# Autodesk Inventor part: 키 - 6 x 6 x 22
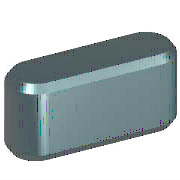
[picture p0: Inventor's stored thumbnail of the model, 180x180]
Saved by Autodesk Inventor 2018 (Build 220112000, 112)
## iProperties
IsCustomPart: 1
Created: 2012-02
Part Number: 키 - 6 x 6 x 22
Material: 강철, 연강
Description: 키 및 해당 키홈
Document SubType Name: Modeling
Standard: KS B 1311
Designer: mduedu
Standards Organization: KS
Language: ko-KR
Size Designation: 6 x 6 x 22
Categories: <MemberInstance><Categories><Category DisplayName="샤프트 부품" InternalName="7f7aeb1f-a693-4053-b835-cee3144e0d98" Mnemonic="SHFT"><Category DisplayName="키" Interna
Density: 7.86 g/cm^3
Mass: 5.79788 g
Surface Area: 5.294 cm^2
Volume: 0.737644 cm^3
Appearance: 노란색
Author: mduedu
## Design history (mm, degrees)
workplane "Work Plane1"
workplane "Work Plane2"
sketch "스케치1"
  geometry: L1 (3, 3)-(19, 3); L2 (19, -3)-(3, -3); L3 (0, 9.4)-(0, -7.4) reference; L4 (-5, 0)-(30, 0) reference; L5 (22, 0)-(22, 7); A1 r 3 centre (3, 0) between (3, 3) and (3, -3); A2 r 3 centre (19, 0) between (19, -3) and (19, 3)
  constraints: 6 end point, 5 point on circle, 4 tangent, 3 point on line, 2 centre point, 1 horizontal, 1 parallel, 1 perpendicular
  dimensions: "d0" = 3 radius of A1 (= 0.5 x PB); "d13" = 3 radius of A2 (= 0.5 x PB); "d14" = 22 distance between parallel lines of L5 L3 (= NLG)
extrude "본체1" new body sketch "스케치1" taper "d3" = 0 deg; stored distance "d4" = 10
workplane "Work Plane3"
body "Solid1"
chamfer "모따기1" distance "d8" = 0.4 (= PHH); stored, may be unused: second distance "d9" = 0.4 (= PHH), angle "d15" = 45 deg
other parameters: "d1" = -3.5 (= -PNT), "d2" = 2.5 (= PH - PNT), "NLG" = 22 [user parameter; used in 3 equation terms], "PB" = 6 [user parameter; used in 2 equation terms], "PNT" = 3.5 [user parameter; used in 2 equation terms], "PH" = 6 [user parameter; used in 1 equation term], "PHH" = 0.4 [user parameter; used in 2 equation terms], "d10" = 0, "d16" = 0, "d17" = 0, "d18" = 0, "WDMIN" = 17 [user parameter], "PLB2" = 22 (= NLG) [user parameter], "WDMAX" = 22 [user parameter], "PLB1" = 22 (= NLG) [user parameter], "RR" = 0.16 [user parameter], "PUEB" = 2.8 [user parameter]
